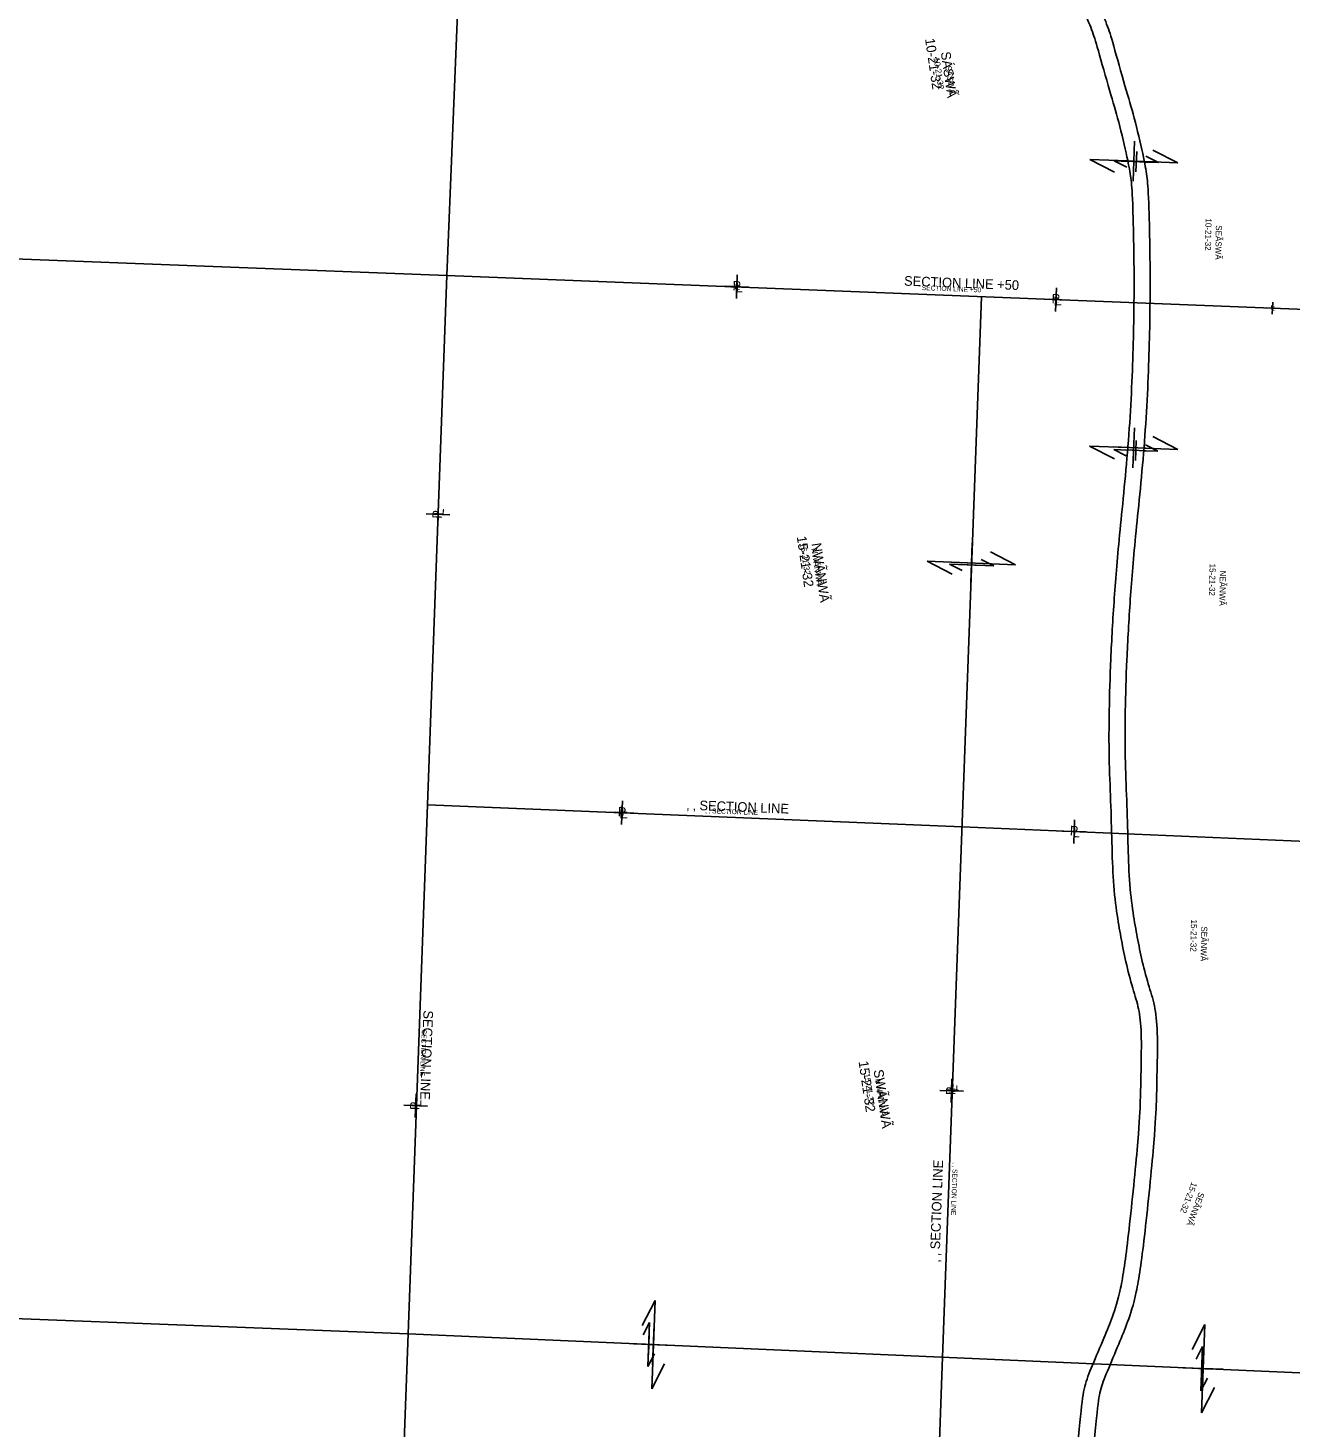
# Model space of a CAD drawing. Extents: x 2814293 to 2835768, y 121185 to 156337.
# Drawn here: x 2820000 to 2823143, y 138763 to 142248 of the extents above; entities that cross this region are included whole.
import ezdxf

# ---------------------------------------------------------------- set-up
doc = ezdxf.new("R2010")
doc.units = 0
for name, color, linetype in [('Default', 7, 'Continuous'), ('Photo-Retaining wall', 7, 'Continuous'), ('Roadway-Alignment notes', 7, 'Continuous'), ('Roadway-Edge of pavement', 7, 'Continuous'), ('Roadway-Edge of shoulder', 7, 'Continuous'), ('Roadway-Entrances', 7, 'Continuous'), ('Roadway-Safety', 7, 'Continuous'), ('Roadway-Walls', 7, 'Continuous'), ('Scratch-2', 7, 'Continuous'), ('Scratch-5', 7, 'Continuous'), ('Traffic_Control-Traffic barriers', 7, 'Continuous')]:
    doc.layers.add(name, color=color, linetype=linetype)

msp = doc.modelspace()

# ---------------------------------------------------------------- linework, layer by layer
at = {"layer": 'Default'}
for p, q in [((2822753.7, 141966.9), (2822749.9, 141866.9)), ((2822701.8, 141918.8), (2822801.8, 141915)), ((2822733, 141916.6), (2822782.9, 141914.7)), ((2822758.9, 141940.6), (2822757, 141890.6)), ((2822753.5, 141253.4), (2822749.6, 141153.5)), ((2822757.7, 141221.9), (2822755.8, 141171.9)), ((2822701.6, 141205.4), (2822801.5, 141201.5)), ((2822731.7, 141197.9), (2822781.7, 141195.9))]:
    msp.add_line(p, q, dxfattribs=at)
at = {"layer": 'Roadway-Edge of pavement'}
for p, q in [((2822734.1, 141901.8), (2822703, 141917.8)), ((2822737.1, 141916.4), (2822703, 141917.8)), ((2822757.9, 141915.6), (2822757.9, 141915.6)), ((2822812.9, 141913.5), (2822778.2, 141914.8)), ((2822781.8, 141929.5), (2822812.9, 141913.5)), ((2822732.9, 141183), (2822701.8, 141199)), ((2822736.5, 141197.7), (2822701.8, 141199)), ((2822756.7, 141196.9), (2822756.7, 141196.9)), ((2822811.7, 141194.8), (2822776.5, 141196.1)), ((2822780.6, 141210.8), (2822811.7, 141194.8)), ((2822403, 140909.6), (2822293.1, 140913.8)), ((2822324.2, 140897.8), (2822293.1, 140913.8)), ((2822323, 140912.6), (2822373, 140910.7)), ((2822349, 140936.7), (2822347.1, 140886.7)), ((2822348, 140911.7), (2822348, 140911.7)), ((2822371.9, 140925.6), (2822403, 140909.6)), ((2821530.7, 138995.2), (2821546.7, 139026.3)), ((2821542.5, 138916.4), (2821546.7, 139026.3)), ((2821545.5, 138996.4), (2821543.6, 138946.4)), ((2821569.6, 138970.4), (2821519.6, 138972.4)), ((2821544.6, 138971.4), (2821544.6, 138971.4)), ((2822907, 138934.8), (2822923, 138965.9)), ((2822918.8, 138856), (2822923, 138965.9)), ((2821558.5, 138947.5), (2821542.5, 138916.4)), ((2822921.9, 138935.9), (2822919.9, 138885.9)), ((2822945.9, 138910), (2822895.9, 138911.9)), ((2822934.8, 138887.1), (2822918.8, 138856)), ((2822920.9, 138910.9), (2822920.9, 138910.9))]:
    msp.add_line(p, q, dxfattribs=at)
at = {"layer": 'Roadway-Edge of shoulder'}
for p, q in [((2821734.4, 141605.5), (2821793.2, 141603.3)), ((2821765, 141633.8), (2821762.7, 141575)), ((2822559, 141601.7), (2822556.7, 141542.8)), ((2822528.4, 141573.4), (2822587.3, 141571.1)), ((2821019.3, 141008.3), (2821021.6, 141067.1)), ((2820991, 141038.8), (2821049.9, 141036.6)), ((2821479.3, 140324.4), (2821477, 140265.5)), ((2821448.7, 140296.1), (2821507.6, 140293.8)), ((2822604.3, 140277.6), (2822602.1, 140218.7)), ((2822573.8, 140249.3), (2822632.6, 140247)), ((2822297.1, 139573.2), (2822299.2, 139632.1)), ((2820963.3, 139536), (2820965.6, 139594.9)), ((2822268.7, 139603.7), (2822327.6, 139601.7)), ((2820935, 139566.6), (2820993.9, 139564.3))]:
    msp.add_line(p, q, dxfattribs=at)
at = {"layer": 'Roadway-Entrances'}
for p, q in [((2821042.3, 141632.4), (2821148.7, 144280.6)), ((2815737.9, 141835.4), (2821042.4, 141632.2)), ((2821042.3, 141632.4), (2820945.5, 138997.4)), ((2823703.8, 141527.1), (2821042.3, 141632.4)), ((2822373.1, 141579.5), (2822275.4, 138939.5)), ((2820993.9, 140314.8), (2822324.3, 140259.5)), ((2822324.3, 140259.5), (2823655.2, 140203.8)), ((2820945.5, 138997.4), (2818251, 139103.7)), ((2820945.5, 138997.4), (2820848.6, 136362.6)), ((2823605.3, 138881.7), (2820945.5, 138997.4)), ((2822275.4, 138939.5), (2822227.8, 137625.4))]:
    msp.add_line(p, q, dxfattribs=at)
at = {"layer": 'Roadway-Walls'}
for p, q in [((2821748.8, 141604.2), (2821778.2, 141603)), ((2821764.1, 141618.3), (2821762.9, 141588.9)), ((2822543, 141573), (2822572.4, 141571.8)), ((2822558.3, 141587.1), (2822557.1, 141557.7)), ((2823097.4, 141565.6), (2823096.3, 141536.2)), ((2823082.2, 141551.5), (2823111.6, 141550.3)), ((2821476.9, 140310.4), (2821475.8, 140281)), ((2821461.6, 140296.3), (2821491.1, 140295.1)), ((2822301, 139619), (2822299.9, 139589.5)), ((2822315.1, 139603.7), (2822285.7, 139604.7))]:
    msp.add_line(p, q, dxfattribs=at)
at = {"layer": 'Scratch-2'}
for p, q in [((2822704.1, 141889.1), (2822641.9, 141921.2)), ((2822736.9, 141917.5), (2822641.9, 141921.2)), ((2822751.8, 141916.9), (2822751.8, 141916.9)), ((2822861.7, 141912.6), (2822778, 141915.9)), ((2822799.5, 141944.6), (2822861.7, 141912.6)), ((2822799.2, 141231.2), (2822861.4, 141199.2)), ((2822703.8, 141175.7), (2822641.6, 141207.7)), ((2822737, 141204), (2822641.6, 141207.7)), ((2822751.5, 141203.4), (2822751.5, 141203.4)), ((2822861.4, 141199.2), (2822777, 141202.5)), ((2822349.7, 140966.6), (2822345.8, 140866.6)), ((2822395.4, 140944.4), (2822457.7, 140912.3)), ((2822457.7, 140912.3), (2822237.8, 140920.9)), ((2822300.1, 140888.8), (2822237.8, 140920.9)), ((2822297.8, 140918.5), (2822397.7, 140914.7)), ((2822347.7, 140916.6), (2822347.7, 140916.6)), ((2821528.5, 139018.3), (2821560.5, 139080.5)), ((2821552, 138860.7), (2821560.5, 139080.5)), ((2822896.7, 138959), (2822928.7, 139021.3)), ((2822920.2, 138801.4), (2822928.7, 139021.3)), ((2821558.2, 139020.6), (2821554.3, 138920.7)), ((2821606.2, 138968.7), (2821506.3, 138972.6)), ((2821556.2, 138970.6), (2821556.2, 138970.6)), ((2822926.4, 138961.3), (2822922.5, 138861.4)), ((2821584, 138922.9), (2821552, 138860.7)), ((2822974.4, 138909.4), (2822874.5, 138913.3)), ((2822924.4, 138911.4), (2822924.4, 138911.4)), ((2822952.2, 138863.7), (2822920.2, 138801.4))]:
    msp.add_line(p, q, dxfattribs=at)
at = {"layer": 'Traffic_Control-Traffic barriers'}
for points in [[(2822619.1, 138791.9), (2822623.3, 138830.4), (2822627.9, 138868.3), (2822646.1, 138913.9), (2822679.5, 138992.1), (2822698.2, 139038.1), (2822719.4, 139101.6), (2822737.2, 139223.3), (2822763.5, 139483.6), (2822768.3, 139574.7), (2822769.1, 139633.3), (2822771.8, 139741.2), (2822766.3, 139803.1), (2822752.2, 139846.7), (2822732.7, 139917), (2822721, 139977.9), (2822710.3, 140035.7), (2822699.8, 140123), (2822697.3, 140218.9), (2822694.4, 140324.5), (2822689.5, 140431.6), (2822690.1, 140547.7), (2822693.6, 140672.5), (2822702.4, 140829), (2822715.6, 140985.8), (2822740.8, 141221.6), (2822751.4, 141457.2), (2822753.3, 141653.7), (2822748.8, 141833.4), (2822745, 141874), (2822737.3, 141918.3), (2822713.5, 142020.4), (2822693.8, 142083.7), (2822659.6, 142205.9), (2822649.1, 142240.5), (2822624.5, 142298.2), (2822593.7, 142351.1), (2822546.4, 142430.7), (2822480.1, 142534), (2822463.8, 142556.3), (2822446.4, 142602), (2822438.8, 142652.6), (2822442.7, 142678), (2822446.2, 142737), (2822450.6, 142792.4), (2822454, 142807.1), (2822446.8, 142851.5), (2822427.2, 142951.1), (2822416.1, 143016.1), (2822396, 143092), (2822385, 143134), (2822371.9, 143173.6), (2822345.3, 143244.4), (2822326.3, 143328.8), (2822294.5, 143488.6), (2822269.4, 143698.3), (2822273.3, 143914), (2822277.1, 144153.7), (2822287.1, 144167.5), (2822301.3, 144227.5), (2822303.2, 144254.3), (2822314.9, 144351.8), (2822321.1, 144393.5), (2822335.7, 144491.2), (2822346, 144536.6), (2822373.7, 144643.1), (2822393.2, 144703.5), (2822408.7, 144750), (2822424.4, 144796.1), (2822459.5, 144878.5), (2822488.1, 144956.1), (2822504, 144993.2), (2822518.1, 145038.9), (2822525.7, 145096), (2822523.6, 145130.9), (2822521.2, 145154.4)], [(2822658.9, 138787.6), (2822663, 138825.8), (2822667, 138858.3), (2822683.1, 138898.6), (2822716.4, 138976.7), (2822735.8, 139024.2), (2822758.5, 139092.3), (2822776.9, 139218.4), (2822803.4, 139480.5), (2822808.3, 139573.4), (2822809.1, 139632.5), (2822811.8, 139742.5), (2822805.8, 139811.1), (2822790.5, 139858.2), (2822771.7, 139926.1), (2822760.3, 139985.4), (2822749.8, 140041.7), (2822739.7, 140125.9), (2822737.3, 140219.9), (2822734.4, 140325.9), (2822729.5, 140432.4), (2822730.1, 140547), (2822733.6, 140670.8), (2822742.3, 140826.2), (2822755.4, 140982), (2822780.7, 141218.6), (2822791.4, 141456.1), (2822793.3, 141654), (2822788.7, 141835.7), (2822784.7, 141879.2), (2822776.6, 141926.3), (2822752.1, 142030.9), (2822732.2, 142095), (2822698, 142217.1), (2822686.7, 142254.1), (2822660.3, 142316.2), (2822628.2, 142371.4), (2822580.4, 142451.8), (2822513.1, 142556.7), (2822499.3, 142575.6), (2822485.3, 142612.2), (2822479.2, 142652.5), (2822482.5, 142673.7), (2822486.1, 142734.2), (2822490.3, 142786.3), (2822494.7, 142805.8), (2822486.2, 142858.5), (2822466.5, 142958.3), (2822455.3, 143024.6), (2822434.7, 143102.2), (2822423.4, 143145.3), (2822409.7, 143187), (2822383.7, 143255.9), (2822365.4, 143337), (2822334.1, 143494.9), (2822309.5, 143700.3), (2822313.3, 143913.3), (2822317.1, 144155.8), (2822333.6, 144194), (2822340.3, 144212.2), (2822343.1, 144250.5), (2822354.6, 144346.5), (2822360.7, 144387.6), (2822375, 144483.8), (2822384.9, 144527.1), (2822412.2, 144631.9), (2822431.2, 144691), (2822446.6, 144737.2), (2822461.8, 144781.8), (2822496.7, 144863.7), (2822525.3, 144941.3), (2822541.6, 144979.4), (2822557.3, 145030.3), (2822565.3, 145090.5), (2822563.9, 145125.3), (2822562.5, 145142.8)], [(2820421.9, 132323.7), (2820430.3, 132339.5), (2820446.6, 132365.4), (2820477.5, 132409.8), (2820521.7, 132462.2), (2820581.9, 132544.8), (2820633.7, 132622.6), (2820678.7, 132698.5), (2820711.5, 132765.4), (2820823.8, 132974.3), (2820869.5, 133062.1), (2820906.1, 133146.6), (2820945.5, 133258.7), (2820956.4, 133356.9), (2820952.7, 133425), (2820927.9, 133503.2), (2820893.9, 133557.3), (2820809, 133702.5), (2820771.2, 133774.3), (2820745.5, 133846.6), (2820736.3, 133904.7), (2820741, 133953.4), (2820747.2, 134000.7), (2820776.6, 134101.6), (2820833.7, 134304.6), (2820904.5, 134550.3), (2820921.6, 134614.4), (2820930.5, 134682.7), (2820930.5, 134758), (2820923.8, 134863.3), (2820917.2, 134986), (2820914.2, 135053.6), (2820915.6, 135096.1), (2820930, 135192), (2820948.1, 135310.8), (2820956, 135344.7), (2820980.6, 135392.4), (2821001.2, 135416.1), (2821028.4, 135446.7), (2821056.8, 135477.7), (2821080.7, 135513.2), (2821109.6, 135587.8), (2821118.7, 135642.2), (2821136.4, 135738.5), (2821159.1, 135874.6), (2821198.2, 136048.3), (2821218.1, 136218.9), (2821227.9, 136304.7), (2821244.8, 136389.4), (2821276, 136485.3), (2821314.1, 136552.1), (2821350.9, 136605.8), (2821391.6, 136657.6), (2821445.7, 136719.4), (2821474.7, 136755.9), (2821500.8, 136798.9), (2821531.8, 136855.4), (2821562.3, 136913.6), (2821611.3, 136995.1), (2821650.2, 137057.9), (2821673.5, 137084.5), (2821709.9, 137111.3), (2821757.5, 137132.5), (2821832.5, 137158.2), (2821931.7, 137192.9), (2821982.6, 137216.4), (2822021.4, 137239.3), (2822062.8, 137269.2), (2822096.8, 137305.8), (2822172, 137398.1), (2822219.2, 137461.1), (2822236.1, 137494), (2822253.7, 137552.5), (2822267, 137602), (2822284.6, 137644.3), (2822301.1, 137678.7), (2822325.1, 137711.8), (2822343.7, 137737.3), (2822366.9, 137773.8), (2822421.5, 137879), (2822464.2, 137966.1), (2822481.4, 138016.2), (2822492.6, 138043.8), (2822505.3, 138098.1), (2822507.9, 138141.9), (2822510.7, 138203.4), (2822514.5, 138251), (2822522.5, 138286.8), (2822534.9, 138334.4), (2822594.9, 138475.5), (2822624.6, 138559.6), (2822642.4, 138629.9), (2822654.8, 138749.4), (2822658.9, 138787.6)], [(2820745, 134137.3), (2820759.2, 134187.4), (2820796.5, 134319.8), (2820866, 134561), (2820882.3, 134622.2), (2820890.5, 134685.3), (2820890.5, 134756.7), (2820883.9, 134860.9), (2820877.2, 134984), (2820874.1, 135053.3), (2820875.7, 135099.8), (2820890.4, 135198), (2820908.8, 135318.4), (2820918.2, 135358.7), (2820947.2, 135415), (2820971.2, 135442.6), (2820998.7, 135473.5), (2821025.3, 135502.5), (2821045.1, 135531.8), (2821070.8, 135598.4), (2821079.3, 135649.1), (2821097, 135745.4), (2821119.8, 135882.3), (2821158.7, 136055), (2821178.4, 136223.5), (2821188.3, 136310.9), (2821206, 136399.5), (2821239.2, 136501.5), (2821280.2, 136573.3), (2821318.6, 136629.4), (2821360.8, 136683.1), (2821415, 136745), (2821441.8, 136778.8), (2821466.2, 136818.9), (2821496.5, 136874.2), (2821527.4, 136933.2), (2821577.1, 137015.9), (2821617.9, 137081.8), (2821646.4, 137114.1), (2821689.7, 137146.1), (2821742.9, 137169.7), (2821819.5, 137196), (2821916.7, 137230), (2821964, 137251.9), (2821999.5, 137272.8), (2822036.2, 137299.3), (2822066.7, 137332.1), (2822140.5, 137422.7), (2822185.2, 137482.3), (2822198.9, 137509), (2822215.2, 137563.4), (2822229.1, 137614.9), (2822248, 137660.6), (2822266.7, 137699.3), (2822292.7, 137735.3), (2822310.6, 137759.8), (2822332.2, 137793.7), (2822385.8, 137897), (2822427.2, 137981.4), (2822444, 138030.2), (2822454.4, 138055.9), (2822465.5, 138103.9), (2822468, 138144.1), (2822470.8, 138205.9), (2822474.8, 138257), (2822483.6, 138296.3), (2822497, 138347.3), (2822557.6, 138490), (2822586.2, 138571.2), (2822602.9, 138636.9), (2822615, 138753.6), (2822619.1, 138791.9)]]:
    msp.add_open_spline(points, degree=3, dxfattribs=at)

# ---------------------------------------------------------------- texts
at = {"layer": 'Photo-Retaining wall'}
for s, rotation, p in [('10-21-32', 278.3561, (2822253.3, 142174.1)), ('SÁSWÃ', 278.3561, (2822282.5, 142154.1)), ('10-21-32', 268.849, (2822930.4, 141774.6)), ('SEÃSWÃ', 268.849, (2822956.1, 141757.5)), ('15-21-32', 278.3561, (2821921, 140965.4)), ('NWÃNWÃ', 278.3561, (2821949.1, 140952.8)), ('15-21-32', 268.849, (2822940.4, 140915.1)), ('NEÃNWÃ', 268.849, (2822966.1, 140898)), ('15-21-32', 268.849, (2822894.1, 140029.3)), ('SEÃNWÃ', 268.849, (2822919.7, 140012.2)), ('15-21-32', 278.3561, (2822080.3, 139644.6)), ('NWÃNWÃ', 278.3561, (2822108.4, 139632)), ('15-21-32', 248.849, (2822895.9, 139376.5)), ('SEÃNWÃ', 248.849, (2822914.1, 139351.6))]:
    msp.add_text(s, height=15, rotation=rotation, dxfattribs=at).set_placement(p)
at = {"layer": 'Roadway-Alignment notes'}
for s, p in [('10-21-32', (2822232.1, 142221.1)), ('SÁSWÃ', (2822271.3, 142187.9)), ('15-21-32', (2821912.9, 140982.1)), ('NWÃNWÃ', (2821949.8, 140964.9)), ('15-21-32', (2822066.6, 139675.4)), ('SWÃNWÃ', (2822104.1, 139654.1))]:
    msp.add_text(s, height=24, rotation=278.3561, dxfattribs=at).set_placement(p)
at = {"layer": 'Roadway-Edge of shoulder'}
for s, rotation, p in [('P', 357.7804, (2821752.8, 141595.2)), ('L', 357.7804, (2821760.6, 141590.6)), ('P', 357.7804, (2822546.8, 141563.1)), ('L', 357.7804, (2822554.6, 141558.5)), ('P', 87.7804, (2821029.6, 141026.7)), ('L', 87.7804, (2821034.2, 141034.5)), ('P', 357.7804, (2821467.1, 140285.8)), ('L', 357.7804, (2821475, 140281.2)), ('P', 357.7804, (2822592.2, 140238.9)), ('L', 357.7804, (2822600, 140234.3)), ('L', 87.9775, (2822312, 139599.5)), ('L', 87.7804, (2820978.3, 139562.2)), ('P', 87.9775, (2822307.4, 139591.7)), ('P', 87.7804, (2820973.7, 139554.4))]:
    msp.add_text(s, height=23.6, rotation=rotation, dxfattribs=at).set_placement(p)
at = {"layer": 'Roadway-Safety'}
for s, rotation, p in [('SECTION LINE +50', 357.7804, (2822224, 141596)), ('‚ ‚ SECTION LINE', 357.7804, (2821685.5, 140294.2)), ('SECTION LINE', 267.8429, (2820979.9, 139754.8)), ('‚ ‚ SECTION LINE', 267.99, (2822301.4, 139424.6))]:
    msp.add_text(s, height=12, rotation=rotation, dxfattribs=at).set_placement(p)
at = {"layer": 'Roadway-Walls'}
for s, rotation, p in [('P', 357.7804, (2821758, 141599)), ('L', 357.7804, (2821761.9, 141596.7)), ('P', 357.7804, (2822552.2, 141567.8)), ('L', 357.7804, (2822556.1, 141565.5)), ('P', 357.7804, (2823091.4, 141546.3)), ('L', 357.7804, (2823095.3, 141544)), ('P', 357.7804, (2821470.8, 140291.1)), ('L', 357.7804, (2821474.8, 140288.8)), ('L', 267.9775, (2822293.5, 139605.8)), ('P', 267.9775, (2822295.8, 139609.7))]:
    msp.add_text(s, height=11.8, rotation=rotation, dxfattribs=at).set_placement(p)
at = {"layer": 'Scratch-5'}
for s, rotation, p in [('SECTION LINE +50', 357.7804, (2822179.6, 141607.1)), ('‚ ‚ SECTION LINE', 357.7804, (2821638.3, 140302.6)), ('SECTION LINE', 267.8429, (2820984, 139803.3)), ('‚ ‚ SECTION LINE', 87.99, (2822268.2, 139175.6))]:
    msp.add_text(s, height=24, rotation=rotation, dxfattribs=at).set_placement(p)

doc.saveas('drawing.dxf')
